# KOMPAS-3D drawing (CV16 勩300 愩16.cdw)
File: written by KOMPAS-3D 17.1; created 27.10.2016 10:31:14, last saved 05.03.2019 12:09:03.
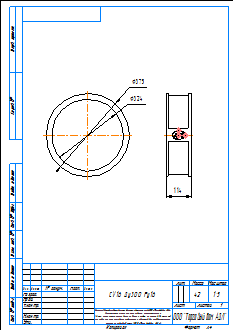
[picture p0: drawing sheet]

Sheet 1: A4, portrait

Title block, sheet 1: name: CV16 Ду300 Ру16; material: Сталь 20  ГОСТ 1050-88; mass: 42; sheets: 1; sheet format: A4; stored path: \\adlc.lan\data\АДЛ_ПКД\3D-модели\ADL production\Клапаны обратные ГРАНЛОК\CV16\KOMPAS 2D\CV16 Ду300 Ру16.cdw

Views: Вид 1, Проекционный вид 2
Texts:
  Klimkovich
  ADL
  Рама для чертежей
  Лит-Масса-Масштаб
  Материал-Предприятие
  Масштаб
  Изм.
  Лист
  № докум.
  Подп.
  Дата
  Лит.
  Разраб.
  Пров.
  Т.контр.
  Листов
  Внимание! Данный продукт является объектом авторского права ООО «Торговый Дом АДЛ».
  Запрещается изменение, копирование, распространение
  (в том числе путем копирования на другие сайты и ресурсы в Интернете)
  или любое иное использование информации и объектов без предварительного
  согласия правообладателя (ООО «Торговый Дом АДЛ»).
  Н.контр.
  Утв.
  ООО "Торговый дом АДЛ"
  Изменение
  Номер документа
  Подпись
  Обозначение документа
  Наименование изделия
  Масса изделия по ГОСТ 2.109-73
  Порядковый номер листа
  Общее количество листов в документе
  Характер работы, выполненной лицом, подписавшим документ
  Наименование или индекс предприятия, выпускающего документ
  Инв. № подл.
  Подп. и дата
  Взам. инв. №
  Инв. № дубл.
  Инвентарный номер подлинника по ГОСТ 2.501-68
  Подпись принявшего подлинник в отдел технической документации
  Инвентарный номер подлинника, взамен которого выпущен данный подлинник
  Инвентарный номер дубликата по ГОСТ 2.502-68
  Подпись принявшего дубликат в отдел технической документации
  Справ. №
  Перв. примен.
  Обозначение документа, взамен или на основании которого выпущен данный документ
  Обозначение документа, в котором впервые записан данный документ
  Подпись лица, копировавшего чертеж
  Обозначение формата листа
  !Рама для чертежа
Dimensions and other numbers on the sheet: 375; 324; 114; 1:5; 1; 42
